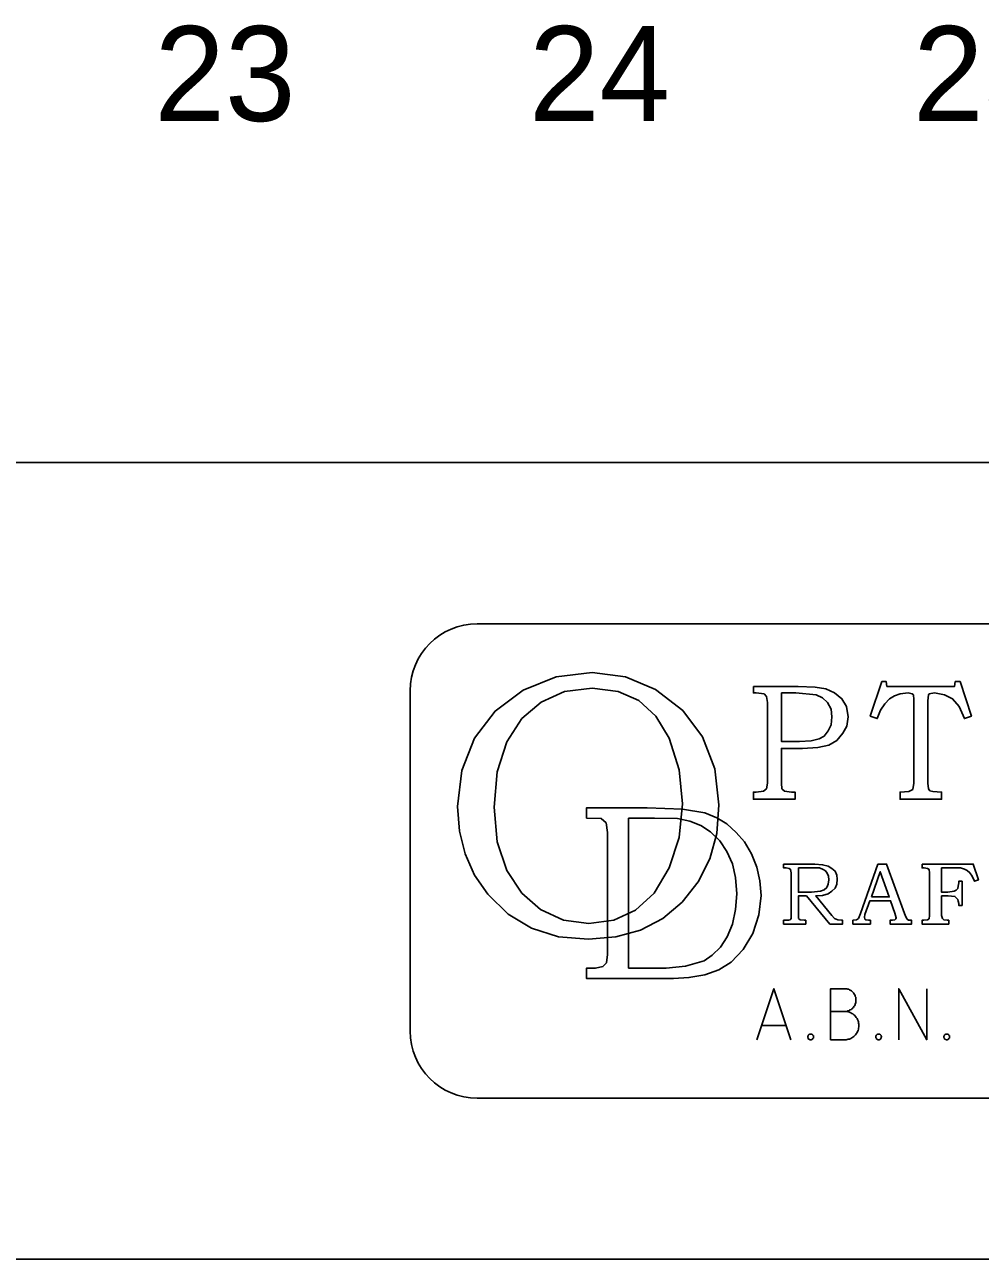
# Model space of a CAD drawing. Extents: x 0 to 841, y 0 to 594.
# Drawn here: x 489.7 to 540.1, y 15 to 80.1 of the extents above; entities that cross this region are included whole.
import ezdxf

# ---------------------------------------------------------------- set-up
doc = ezdxf.new("R2010")
doc.units = 0
for name, color, linetype in [('A1BORDER', 7, 'Continuous'), ('Level 1', 7, 'Continuous'), ('Level 10', 7, 'Continuous')]:
    doc.layers.add(name, color=color, linetype=linetype)

msp = doc.modelspace()

# ---------------------------------------------------------------- linework, layer by layer
at = {"layer": 'A1BORDER'}
for p, q in [((28, 57), (829, 57)), ((829, 15), (28, 15))]:
    msp.add_line(p, q, dxfattribs=at)
at = {"layer": 'Level 1'}
for points in [[(519.59, 45.93), (517.69, 45.7), (515.96, 45), (514.48, 43.9), (513.4, 42.47), (512.73, 40.77), (512.5, 38.87), (512.6, 37.57), (512.9, 36.37), (513.39, 35.25), (514.1, 34.25), (515.17, 33.2), (516.4, 32.45), (517.82, 32), (519.4, 31.87), (520.84, 32), (522.14, 32.35), (523.32, 32.97), (524.34, 33.83), (525.19, 34.9), (525.8, 36.1), (526.17, 37.45), (526.28, 38.95), (526.07, 40.85), (525.42, 42.53), (524.37, 43.93), (522.94, 45.03), (521.36, 45.7)], [(519.6, 45.1), (520.96, 44.93), (522.06, 44.45), (522.96, 43.63), (523.66, 42.47), (524.18, 40.8), (524.36, 39), (524.18, 37.23), (523.66, 35.63), (522.86, 34.3), (521.88, 33.4), (520.73, 32.87), (519.42, 32.7), (518.08, 32.87), (516.88, 33.43), (515.88, 34.3), (515.1, 35.5), (514.59, 37), (514.43, 38.83), (514.59, 40.7), (515.1, 42.27), (515.89, 43.5), (516.9, 44.37), (518.14, 44.93)], [(519.3, 38.25), (520.07, 38.23), (520.34, 38), (520.4, 37.5), (520.4, 31.07), (520.36, 30.63), (520.16, 30.43), (519.78, 30.35), (519.67, 30.35), (519.3, 30.35), (519.3, 29.8), (523.88, 29.8), (524.7, 29.85), (525.53, 30), (526.28, 30.25), (526.93, 30.67), (527.56, 31.33), (528.06, 32.17), (528.38, 33.15), (528.5, 34.17), (528.44, 34.95), (528.28, 35.67), (528, 36.37), (527.62, 37), (527.18, 37.5), (526.7, 37.95), (526.16, 38.27), (525.54, 38.53), (524.36, 38.73), (522.5, 38.8), (519.3, 38.8)], [(521.52, 30.35), (521.52, 38.25), (522.88, 38.25), (524.09, 38.23), (524.74, 38.1), (525.32, 37.87), (525.84, 37.53), (526.32, 37.05), (526.7, 36.5), (526.99, 35.85), (527.16, 35.13), (527.22, 34.27), (527.16, 33.43), (526.99, 32.67), (526.72, 32), (526.36, 31.45), (525.93, 31.03), (525.5, 30.73), (524.52, 30.45), (523.5, 30.35)], [(529.69, 35.83), (529.69, 35.63), (529.82, 35.63), (529.98, 35.6), (530.06, 35.55), (530.09, 35.37), (530.09, 33.13), (530.08, 32.97), (530.03, 32.9), (529.96, 32.87), (529.8, 32.87), (529.69, 32.87), (529.69, 32.67), (530.86, 32.67), (530.86, 32.87), (530.77, 32.87), (530.56, 32.9), (530.48, 32.97), (530.47, 33.13), (530.47, 34.15), (530.89, 34.15), (532.13, 32.67), (532.8, 32.67), (532.8, 32.87), (532.74, 32.87), (532.54, 32.9), (532.37, 32.97), (532.23, 33.13), (531.38, 34.15), (531.74, 34.17), (532.03, 34.27), (532.24, 34.4), (532.4, 34.57), (532.49, 34.77), (532.52, 35.03), (532.49, 35.25), (532.4, 35.45), (532.24, 35.6), (532.04, 35.73), (531.74, 35.8), (531.33, 35.83)], [(534.66, 35.83), (533.74, 33.23), (533.63, 32.97), (533.53, 32.9), (533.34, 32.87), (533.34, 32.67), (534.27, 32.67), (534.27, 32.87), (534.18, 32.87), (534.03, 32.9), (533.98, 32.93), (533.96, 33.03), (533.98, 33.17), (534.24, 33.9), (535.33, 33.9), (535.56, 33.25), (535.63, 33), (535.6, 32.95), (535.56, 32.9), (535.42, 32.87), (535.3, 32.87), (535.3, 32.67), (536.44, 32.67), (536.44, 32.87), (536.39, 32.87), (536.28, 32.87), (536.2, 32.93), (536.13, 33.05), (536.06, 33.23), (535.12, 35.83)], [(536.99, 35.83), (536.99, 35.63), (537.1, 35.63), (537.28, 35.6), (537.36, 35.55), (537.38, 35.37), (537.38, 33.13), (537.36, 32.95), (537.28, 32.9), (537.08, 32.87), (536.99, 32.87), (536.99, 32.67), (538.4, 32.67), (538.4, 32.87), (538.32, 32.87), (538.13, 32.9), (538.06, 32.97), (538.02, 33.13), (538.02, 34.15), (538.37, 34.15), (538.72, 34.13), (538.87, 33.97), (538.9, 33.87), (538.92, 33.75), (538.92, 33.65), (539.1, 33.65), (539.1, 34.93), (538.92, 34.93), (538.92, 34.85), (538.9, 34.67), (538.87, 34.55), (538.79, 34.45), (538.69, 34.4), (538.34, 34.35), (538.02, 34.35), (538.02, 35.63), (538.72, 35.63), (539.02, 35.63), (539.22, 35.57), (539.37, 35.5), (539.5, 35.37), (539.63, 35.2), (539.76, 34.93), (539.96, 35), (539.69, 35.83)], [(530.47, 35.63), (531.33, 35.63), (531.59, 35.63), (531.77, 35.55), (531.89, 35.47), (531.99, 35.35), (532.06, 35.2), (532.07, 35), (532.04, 34.77), (531.97, 34.6), (531.82, 34.47), (531.64, 34.4), (531.16, 34.35), (530.47, 34.35)], [(534.32, 34.1), (534.78, 35.43), (535.26, 34.1)]]:
    msp.add_lwpolyline(points, close=True, dxfattribs=at)
for points in [[(528.28, 26.57), (529.18, 29.26), (530.07, 26.57)], [(532.17, 28.06), (532.9, 28.06), (532.98, 28.06), (533.04, 28.06), (533.1, 28.04), (533.17, 28.03), (533.23, 28), (533.28, 27.96), (533.34, 27.93), (533.39, 27.89), (533.44, 27.85), (533.48, 27.8), (533.52, 27.75), (533.56, 27.69), (533.59, 27.64), (533.62, 27.57), (533.63, 27.51), (533.64, 27.45), (533.66, 27.39), (533.66, 27.33), (533.66, 27.25), (533.64, 27.19), (533.63, 27.13), (533.62, 27.06), (533.59, 27), (533.56, 26.95), (533.52, 26.89), (533.48, 26.84), (533.44, 26.79), (533.39, 26.75), (533.34, 26.71), (533.28, 26.67), (533.23, 26.64), (533.17, 26.61), (533.1, 26.6), (533.04, 26.59), (532.98, 26.57), (532.9, 26.57), (532.17, 26.57), (532.17, 29.26), (532.9, 29.26), (532.96, 29.26), (533.02, 29.25), (533.07, 29.24), (533.12, 29.23), (533.17, 29.2), (533.2, 29.19), (533.26, 29.15), (533.29, 29.13), (533.33, 29.09), (533.37, 29.05), (533.4, 29.01), (533.43, 28.96), (533.46, 28.91), (533.47, 28.86), (533.49, 28.81), (533.49, 28.77), (533.5, 28.71), (533.5, 28.66), (533.5, 28.61), (533.49, 28.56), (533.49, 28.51), (533.47, 28.46), (533.46, 28.41), (533.43, 28.36), (533.4, 28.33), (533.37, 28.27), (533.33, 28.24), (533.29, 28.2), (533.26, 28.17), (533.2, 28.15), (533.17, 28.13), (533.12, 28.1), (533.07, 28.09), (533.02, 28.07), (532.96, 28.06), (532.9, 28.06)], [(535.76, 26.57), (535.76, 29.26), (537.24, 26.57), (537.24, 29.26)], [(528.58, 27.33), (529.77, 27.33)], [(530.97, 26.73), (530.97, 26.71), (530.97, 26.7), (530.97, 26.69), (530.98, 26.67), (530.98, 26.66), (530.98, 26.65), (530.99, 26.64), (530.99, 26.63), (531, 26.61), (531.02, 26.61), (531.03, 26.6), (531.04, 26.59), (531.06, 26.59), (531.07, 26.59), (531.08, 26.57), (531.09, 26.57), (531.1, 26.57), (531.12, 26.57), (531.13, 26.57), (531.14, 26.57), (531.16, 26.57), (531.17, 26.59), (531.18, 26.59), (531.19, 26.59), (531.2, 26.6), (531.2, 26.61), (531.22, 26.61), (531.23, 26.63), (531.23, 26.64), (531.24, 26.65), (531.26, 26.66), (531.26, 26.67), (531.26, 26.69), (531.27, 26.7), (531.27, 26.71), (531.27, 26.73), (531.27, 26.74), (531.27, 26.75), (531.26, 26.76), (531.26, 26.77), (531.26, 26.79), (531.24, 26.8), (531.23, 26.81), (531.23, 26.81), (531.22, 26.83), (531.2, 26.84), (531.2, 26.85), (531.19, 26.85), (531.18, 26.86), (531.17, 26.86), (531.16, 26.86), (531.14, 26.87), (531.13, 26.87), (531.12, 26.87), (531.1, 26.87), (531.09, 26.87), (531.08, 26.86), (531.07, 26.86), (531.06, 26.86), (531.04, 26.85), (531.03, 26.85), (531.02, 26.84), (531, 26.83), (530.99, 26.81), (530.99, 26.81), (530.98, 26.8), (530.98, 26.79), (530.98, 26.77), (530.97, 26.76), (530.97, 26.75), (530.97, 26.74), (530.97, 26.73)], [(534.56, 26.73), (534.56, 26.71), (534.56, 26.7), (534.56, 26.69), (534.56, 26.67), (534.57, 26.66), (534.57, 26.65), (534.58, 26.64), (534.58, 26.63), (534.59, 26.61), (534.6, 26.61), (534.62, 26.6), (534.63, 26.59), (534.64, 26.59), (534.64, 26.59), (534.66, 26.57), (534.68, 26.57), (534.69, 26.57), (534.7, 26.57), (534.72, 26.57), (534.73, 26.57), (534.74, 26.57), (534.76, 26.59), (534.77, 26.59), (534.78, 26.59), (534.78, 26.6), (534.79, 26.61), (534.8, 26.61), (534.82, 26.63), (534.82, 26.64), (534.83, 26.65), (534.83, 26.66), (534.84, 26.67), (534.84, 26.69), (534.84, 26.7), (534.84, 26.71), (534.86, 26.73), (534.84, 26.74), (534.84, 26.75), (534.84, 26.76), (534.84, 26.77), (534.83, 26.79), (534.83, 26.8), (534.82, 26.81), (534.82, 26.81), (534.8, 26.83), (534.79, 26.84), (534.78, 26.85), (534.78, 26.85), (534.77, 26.86), (534.76, 26.86), (534.74, 26.86), (534.73, 26.87), (534.72, 26.87), (534.7, 26.87), (534.69, 26.87), (534.68, 26.87), (534.66, 26.86), (534.64, 26.86), (534.64, 26.86), (534.63, 26.85), (534.62, 26.85), (534.6, 26.84), (534.59, 26.83), (534.58, 26.81), (534.58, 26.81), (534.57, 26.8), (534.57, 26.79), (534.56, 26.77), (534.56, 26.76), (534.56, 26.75), (534.56, 26.74), (534.56, 26.73)], [(538.14, 26.73), (538.14, 26.71), (538.14, 26.7), (538.14, 26.69), (538.16, 26.67), (538.16, 26.66), (538.16, 26.65), (538.17, 26.64), (538.17, 26.63), (538.18, 26.61), (538.19, 26.61), (538.2, 26.6), (538.22, 26.59), (538.23, 26.59), (538.24, 26.59), (538.26, 26.57), (538.27, 26.57), (538.28, 26.57), (538.29, 26.57), (538.3, 26.57), (538.32, 26.57), (538.33, 26.57), (538.34, 26.59), (538.36, 26.59), (538.37, 26.59), (538.38, 26.6), (538.38, 26.61), (538.39, 26.61), (538.4, 26.63), (538.4, 26.64), (538.42, 26.65), (538.43, 26.66), (538.43, 26.67), (538.43, 26.69), (538.44, 26.7), (538.44, 26.71), (538.44, 26.73), (538.44, 26.74), (538.44, 26.75), (538.43, 26.76), (538.43, 26.77), (538.43, 26.79), (538.42, 26.8), (538.4, 26.81), (538.4, 26.81), (538.39, 26.83), (538.38, 26.84), (538.38, 26.85), (538.37, 26.85), (538.36, 26.86), (538.34, 26.86), (538.33, 26.86), (538.32, 26.87), (538.3, 26.87), (538.29, 26.87), (538.28, 26.87), (538.27, 26.87), (538.26, 26.86), (538.24, 26.86), (538.23, 26.86), (538.22, 26.85), (538.2, 26.85), (538.19, 26.84), (538.18, 26.83), (538.17, 26.81), (538.17, 26.81), (538.16, 26.8), (538.16, 26.79), (538.16, 26.77), (538.14, 26.76), (538.14, 26.75), (538.14, 26.74), (538.14, 26.73)]]:
    msp.add_lwpolyline(points, dxfattribs=at)
at = {"layer": 'Level 10'}
for p, q in [((571.47, 48.5), (513.54, 48.5)), ((510, 44.97), (510, 27.03)), ((513.54, 23.5), (571.47, 23.5)), ((513.54, 23.5), (513.54, 23.5))]:
    msp.add_line(p, q, dxfattribs=at)
for points in [[(528.1, 45.2), (528.1, 44.85), (528.24, 44.85), (528.66, 44.8), (528.79, 44.67), (528.84, 44.35), (528.84, 40.1), (528.79, 39.8), (528.63, 39.67), (528.24, 39.63), (528.1, 39.63), (528.1, 39.25), (530.29, 39.25), (530.29, 39.63), (530.1, 39.63), (529.74, 39.67), (529.6, 39.8), (529.57, 40.1), (529.57, 41.93), (530.68, 41.93), (531.49, 41.97), (532.08, 42.1), (532.49, 42.35), (532.82, 42.73), (533.02, 43.1), (533.09, 43.6), (533, 44.13), (532.76, 44.55), (532.38, 44.85), (531.92, 45.07), (531.36, 45.15), (530.46, 45.2)], [(534.86, 45.45), (534.26, 43.63), (534.63, 43.5), (534.8, 43.95), (535.03, 44.27), (535.28, 44.55), (535.54, 44.7), (535.84, 44.8), (536.26, 44.85), (536.47, 44.8), (536.53, 44.75), (536.56, 44.5), (536.56, 40.1), (536.5, 39.77), (536.29, 39.65), (535.83, 39.63), (535.83, 39.25), (538.02, 39.25), (538.02, 39.63), (537.56, 39.65), (537.4, 39.7), (537.32, 39.8), (537.29, 40.1), (537.29, 44.43), (537.32, 44.75), (537.37, 44.8), (537.64, 44.85), (538.18, 44.75), (538.6, 44.55), (538.94, 44.13), (539.22, 43.5), (539.59, 43.63), (538.99, 45.45), (538.74, 45.45), (538.7, 45.2), (535.14, 45.2), (535.1, 45.45)], [(529.57, 44.85), (530.34, 44.85), (531.4, 44.75), (531.74, 44.6), (532, 44.35), (532.19, 44), (532.24, 43.6), (532.19, 43.17), (532.04, 42.85), (531.82, 42.57), (531.56, 42.43), (531.14, 42.33), (530.53, 42.3), (529.57, 42.3)]]:
    msp.add_lwpolyline(points, close=True, dxfattribs=at)
for centre, start, end in [((513.535, 44.963), 90, 180), ((513.535, 27.03), 180, 270)]:
    msp.add_arc(centre, 3.535, start, end, dxfattribs=at)

# ---------------------------------------------------------------- texts
at = {"layer": 'Level 1'}
for s, p in [('23', (496.517, 75)), ('24', (516.268, 75)), ('25', (536.517, 75))]:
    msp.add_text(s, height=5, dxfattribs=at).set_placement(p)

doc.saveas('drawing.dxf')
